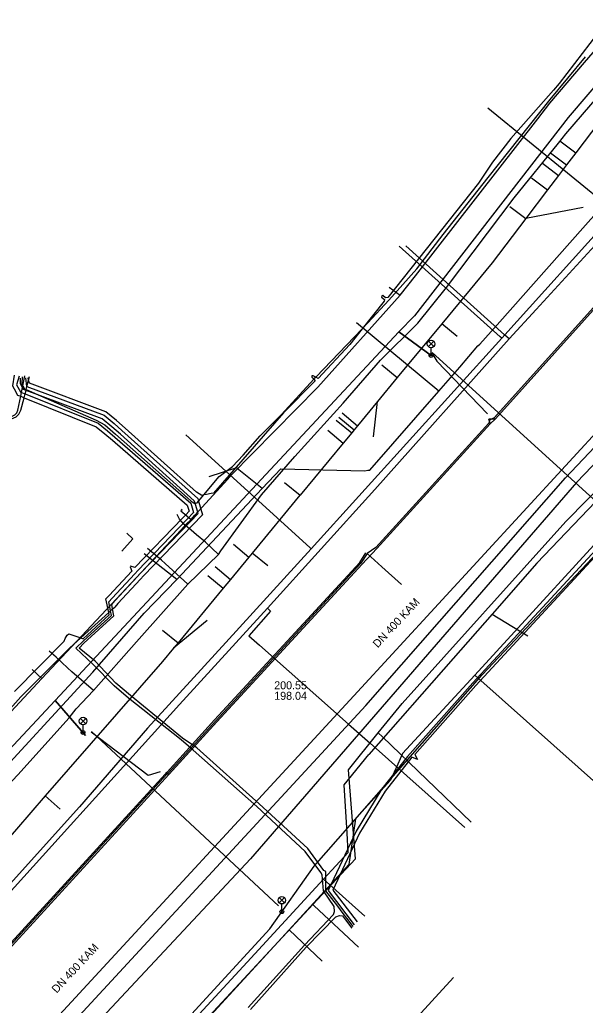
# Model space of a CAD drawing. Extents: x -598932 to -598196, y -1162210 to -1161504.
# Drawn here: x -598529.5 to -598473, y -1161698.8 to -1161600.2 of the extents above; entities that cross this region are included whole.
import ezdxf

# ---------------------------------------------------------------- set-up
doc = ezdxf.new("R2010")
doc.units = 0
for name, color, linetype in [('Vrstva 1', 7, 'Continuous'), ('Vrstva 12', 7, 'Continuous'), ('Vrstva 14', 7, 'Continuous'), ('Vrstva 16', 7, 'Continuous'), ('Vrstva 33', 7, 'Continuous'), ('Vrstva 4', 7, 'Continuous'), ('Vrstva 42', 7, 'Continuous'), ('Vrstva 54', 7, 'Continuous'), ('Vrstva 55', 7, 'Continuous'), ('Vrstva 58', 7, 'Continuous'), ('Vrstva 9', 7, 'Continuous')]:
    doc.layers.add(name, color=color, linetype=linetype)

msp = doc.modelspace()

# ---------------------------------------------------------------- linework, layer by layer
at = {"layer": 'Vrstva 1'}
for p, q in [((-598473.182, -1161619.024), (-598478.906, -1161620.112)), ((-598461.94, -1161630.69), (-598496.1, -1161667.83)), ((-598494.115, -1161641.949), (-598493.723, -1161638.404)), ((-598510.741, -1161660.297), (-598514.118, -1161663.089)), ((-598496.1, -1161667.83), (-598529.33, -1161703.86))]:
    msp.add_line(p, q, dxfattribs=at)
at = {"layer": 'Vrstva 12'}
for p, q in [((-598492.56, -1161626.98), (-598491.47, -1161627.78)), ((-598513.4, -1161651.29), (-598512.9, -1161650.7)), ((-598512.9, -1161650.7), (-598512.34, -1161650.2)), ((-598527.26, -1161666.11), (-598513.4, -1161651.29)), ((-598527.26, -1161666.11), (-598528.25, -1161665.21)), ((-598545.4, -1161685.5), (-598527.26, -1161666.11)), ((-598514.95, -1161704.72), (-598502.57, -1161691.23)), ((-598502.57, -1161691.23), (-598499.25, -1161694.38))]:
    msp.add_line(p, q, dxfattribs=at)
for points in [[(-598477.7, -1161610.13), (-598476.5, -1161608.59), (-598473.05, -1161604.51), (-598471.5, -1161602.74)], [(-598491.47, -1161627.78), (-598489.92, -1161625.84), (-598477.7, -1161610.13)], [(-598433.77, -1161610.9), (-598466.88, -1161647.08), (-598467.08, -1161647.64), (-598467.77, -1161648.05), (-598484.01, -1161665.77)], [(-598512.34, -1161650.2), (-598511.98, -1161649.77), (-598508.73, -1161646.22), (-598508.34, -1161645.78), (-598499.69, -1161636.97), (-598491.47, -1161627.78)], [(-598513.33, -1161649.16), (-598513.25, -1161649.23), (-598513.38, -1161649.33), (-598512.34, -1161650.2)], [(-598484.01, -1161665.77), (-598491.22, -1161673.61), (-598491.7, -1161674.67)], [(-598460.18, -1161686.12), (-598460.61, -1161686.59), (-598484.01, -1161665.77)], [(-598491.7, -1161674.67), (-598492.43, -1161676.27), (-598495.94, -1161680.13), (-598496.6, -1161684.71), (-598502.57, -1161691.23)]]:
    msp.add_lwpolyline(points, dxfattribs=at)
at = {"layer": 'Vrstva 14'}
for points in [[(-598597.949, -1161786.696), (-598594.355, -1161782.22), (-598591.124, -1161778.235), (-598590.488, -1161777.45), (-598568.259, -1161750.324), (-598540.145, -1161717.756), (-598494.895, -1161668.814), (-598474.946, -1161646.048), (-598446.726, -1161616.22), (-598420.512, -1161586.879), (-598391.532, -1161555.529), (-598341.416, -1161505.182)], [(-598573.404, -1161732.925), (-598571.604, -1161731.052), (-598554.514, -1161713.376), (-598533.774, -1161691.098), (-598513.523, -1161668.723), (-598504.735, -1161659.069), (-598494, -1161647.223), (-598480.574, -1161632.154), (-598477.858, -1161629.221), (-598469.826, -1161620.401), (-598456.055, -1161605.679), (-598446.117, -1161594.93), (-598428.638, -1161575.491)], [(-598449.055, -1161597.092), (-598451.08, -1161599.354), (-598469.948, -1161619.476), (-598481.318, -1161632.069), (-598500.359, -1161653.156), (-598508.903, -1161662.52), (-598516.704, -1161671.085), (-598523.517, -1161678.934), (-598531.97, -1161688.321), (-598542.658, -1161699.746), (-598544.581, -1161701.802), (-598554.215, -1161711.962), (-598572.329, -1161730.54), (-598573.411, -1161730.417), (-598574.926, -1161728.994), (-598576.936, -1161727.101), (-598579.192, -1161727.23), (-598579.92, -1161727.954)], [(-598469.948, -1161619.476), (-598470.196, -1161619.273), (-598482.701, -1161609.06)], [(-598589.947, -1161792.741), (-598577.445, -1161777.792), (-598565.596, -1161764.237), (-598559.546, -1161757.337), (-598558.635, -1161756.275), (-598558.918, -1161751.624), (-598555.314, -1161747.837), (-598550.53, -1161742.727), (-598537.985, -1161729.402), (-598525.355, -1161715.849), (-598512.719, -1161702.199), (-598500.184, -1161688.704), (-598495.944, -1161684.141), (-598496.644, -1161675.242), (-598493.647, -1161671.551), (-598491.273, -1161668.615), (-598474.912, -1161650.419), (-598466.442, -1161641.794), (-598445.99, -1161619.606), (-598438.518, -1161611.629), (-598437.483, -1161610.512)], [(-598481.318, -1161632.069), (-598481.459, -1161631.942), (-598491.568, -1161622.876)], [(-598480.574, -1161632.154), (-598480.765, -1161631.978), (-598481.026, -1161631.744), (-598490.91, -1161622.846)], [(-598500.359, -1161653.156), (-598500.505, -1161653.021), (-598512.88, -1161641.744)], [(-598519.28, -1161653.375), (-598518.192, -1161652.151), (-598518.781, -1161651.584)], [(-598504.735, -1161659.069), (-598504.434, -1161659.382), (-598506.575, -1161661.833), (-598505.52, -1161662.78), (-598496.619, -1161670.672), (-598494.477, -1161672.558), (-598485.002, -1161680.994)], [(-598493.647, -1161671.551), (-598493.244, -1161671.942), (-598484.382, -1161680.458)], [(-598500.184, -1161688.704), (-598500.048, -1161688.831), (-598495.639, -1161692.958)]]:
    msp.add_lwpolyline(points, dxfattribs=at)
at = {"layer": 'Vrstva 16'}
for p, q in [((-598487.61, -1161637.39), (-598495.83, -1161630.54)), ((-598513.79, -1161656.2), (-598517.06, -1161653.63)), ((-598499.12, -1161686.18), (-598495, -1161689.86))]:
    msp.add_line(p, q, dxfattribs=at)
for points in [[(-598560.62, -1161703.06), (-598550.73, -1161696.13), (-598543.115, -1161688.089), (-598540.89, -1161685.74), (-598535.99, -1161680.56), (-598535.6, -1161680.12), (-598533.09, -1161677.35), (-598522.17, -1161665.46), (-598517.05, -1161659.56), (-598513.79, -1161656.2), (-598505.27, -1161647.11), (-598503.39, -1161645.14), (-598494.98, -1161645.33), (-598494.68, -1161645.29), (-598494.51, -1161645.26), (-598487.61, -1161637.39), (-598485.51, -1161634.99), (-598483.69, -1161632.85), (-598483.5, -1161632.67), (-598481.515, -1161630.438), (-598473.2, -1161621.09), (-598461.78, -1161608.24)], [(-598466.05, -1161642.27), (-598477.82, -1161654.59), (-598482.27, -1161659.67), (-598486.18, -1161664.12), (-598494.61, -1161673.72)], [(-598505.27, -1161647.11), (-598507.59, -1161645.23), (-598507.83, -1161645.04), (-598510.57, -1161645.95)], [(-598482.27, -1161659.67), (-598479.54, -1161661.33), (-598478.72, -1161661.84)], [(-598511.95, -1161700.1), (-598506.77, -1161694.48), (-598499.12, -1161686.18), (-598496.65, -1161683.49), (-598496.77, -1161681.57), (-598497.07, -1161676.75), (-598494.61, -1161673.72)]]:
    msp.add_lwpolyline(points, dxfattribs=at)
at = {"layer": 'Vrstva 33'}
for p, q in [((-598488.646, -1161632.391), (-598488.116, -1161632.921)), ((-598488.646, -1161632.921), (-598488.116, -1161632.391)), ((-598488.381, -1161633.806), (-598488.381, -1161633.031)), ((-598523.425, -1161670.095), (-598522.895, -1161670.625)), ((-598523.425, -1161670.625), (-598522.895, -1161670.095)), ((-598523.16, -1161671.51), (-598523.16, -1161670.735)), ((-598503.555, -1161688.015), (-598503.025, -1161688.545)), ((-598503.555, -1161688.545), (-598503.025, -1161688.015)), ((-598503.29, -1161689.43), (-598503.29, -1161688.655))]:
    msp.add_line(p, q, dxfattribs=at)
for centre, radius in [((-598488.381, -1161632.656), 0.375), ((-598488.381, -1161633.806), 0.19), ((-598488.381, -1161633.806), 0.05), ((-598523.16, -1161670.36), 0.375), ((-598523.16, -1161671.51), 0.19), ((-598523.16, -1161671.51), 0.05), ((-598503.29, -1161688.28), 0.375), ((-598503.29, -1161689.43), 0.19), ((-598503.29, -1161689.43), 0.05)]:
    msp.add_circle(centre, radius, dxfattribs=at)
at = {"layer": 'Vrstva 42'}
for p, q in [((-598476.142, -1161607.28), (-598478.125, -1161609.529)), ((-598514.801, -1161675.525), (-598514.655, -1161675.559))]:
    msp.add_line(p, q, dxfattribs=at)
for points in [[(-598514.881, -1161675.495), (-598514.586, -1161675.706), (-598514.544, -1161675.66), (-598509.789, -1161670.451), (-598509.79, -1161670.452), (-598495.271, -1161654.682), (-598493.794, -1161653.11), (-598482.467, -1161640.638), (-598481.951, -1161640.136), (-598458.21, -1161613.742), (-598445.27, -1161599.978), (-598445.069, -1161599.756), (-598441.565, -1161595.287), (-598431.149, -1161583.871), (-598378.675, -1161526.796), (-598362.821, -1161511.358), (-598362.827, -1161511.253), (-598362.686, -1161511.241), (-598356.249, -1161505.182)], [(-598514.881, -1161675.495), (-598514.586, -1161675.706), (-598514.544, -1161675.66), (-598509.789, -1161670.451), (-598509.79, -1161670.452), (-598495.271, -1161654.682), (-598493.794, -1161653.11), (-598482.467, -1161640.638), (-598481.951, -1161640.136), (-598458.21, -1161613.742), (-598445.27, -1161599.978), (-598445.069, -1161599.756), (-598441.565, -1161595.287), (-598431.149, -1161583.871), (-598378.675, -1161526.796), (-598362.821, -1161511.358), (-598362.827, -1161511.253), (-598362.686, -1161511.241), (-598356.249, -1161505.182)], [(-598482.615, -1161640.14), (-598481.951, -1161640.136), (-598458.21, -1161613.742), (-598445.27, -1161599.978), (-598445.069, -1161599.756), (-598441.565, -1161595.287), (-598431.149, -1161583.871), (-598378.675, -1161526.796), (-598362.821, -1161511.358), (-598362.827, -1161511.253), (-598362.686, -1161511.241), (-598356.249, -1161505.182)], [(-598406.04, -1161581.87), (-598407.62, -1161583.94), (-598408.397, -1161584.168), (-598416.793, -1161593.283), (-598421.344, -1161598.244), (-598423.305, -1161600.382), (-598424.039, -1161601.179), (-598432.178, -1161610.025), (-598444.71, -1161623.962), (-598460.94, -1161641.979), (-598483.892, -1161666.804), (-598490.009, -1161673.693), (-598489.744, -1161674.222), (-598490.288, -1161673.987), (-598492.973, -1161677.375), (-598495.513, -1161681.565), (-598498.183, -1161687.257), (-598495.776, -1161690.441)], [(-598468.077, -1161596.787), (-598467.695, -1161597.11), (-598470.55, -1161600.45), (-598471.53, -1161601.39), (-598471.634, -1161601.344), (-598471.955, -1161601.07), (-598472.073, -1161601.107), (-598472.084, -1161601.226), (-598471.768, -1161601.505), (-598471.73, -1161601.61), (-598475.56, -1161606.62), (-598476.142, -1161607.28)], [(-598445.433, -1161599.698), (-598445.423, -1161599.921), (-598458.32, -1161613.64), (-598482.063, -1161640.036), (-598482.553, -1161640.291)], [(-598529.239, -1161635.943), (-598529.267, -1161636.625), (-598529.162, -1161636.839), (-598529.02, -1161637.13), (-598528.835, -1161637.211), (-598527.406, -1161637.838), (-598521.84, -1161640.28), (-598520.987, -1161640.743), (-598519.913, -1161641.664), (-598512.706, -1161648.028), (-598512.353, -1161648.365), (-598512.05, -1161648.59), (-598511.965, -1161648.579), (-598511.75, -1161648.55), (-598511.606, -1161648.379), (-598511.087, -1161647.757), (-598509.54, -1161645.91), (-598508.23, -1161644.91), (-598507.16, -1161643.76), (-598505.45, -1161641.83), (-598503.32, -1161639.71), (-598500.108, -1161636.186), (-598499.989, -1161636.055), (-598499.907, -1161635.97), (-598495.249, -1161631.131), (-598494.69, -1161630.55), (-598492.61, -1161628.29), (-598489.81, -1161625.13), (-598487.17, -1161621.71), (-598482.67, -1161616), (-598476.465, -1161608.22), (-598472.955, -1161603.94)], [(-598478.125, -1161609.529), (-598480.41, -1161612.12), (-598482.25, -1161614.46), (-598483.65, -1161616.59), (-598488.09, -1161622.2), (-598492.69, -1161628.02), (-598492.917, -1161628.04), (-598493.185, -1161627.804), (-598493.297, -1161627.858), (-598493.318, -1161627.976), (-598493.045, -1161628.217), (-598493.07, -1161628.38), (-598495.249, -1161631.131), (-598496.5, -1161632.71), (-598499.666, -1161636.113), (-598499.907, -1161635.97), (-598500.145, -1161635.828), (-598500.282, -1161635.857), (-598500.3, -1161635.986), (-598500.108, -1161636.186), (-598499.962, -1161636.338), (-598503.12, -1161639.53), (-598510.135, -1161647.574)], [(-598577.666, -1161631.059), (-598572.07, -1161632.22), (-598564.36, -1161633.75), (-598554.54, -1161635.71), (-598549.13, -1161636.87), (-598542.19, -1161638.36), (-598534.07, -1161639.91), (-598531.557, -1161640.177), (-598530.727, -1161640.228), (-598530.3, -1161640.13), (-598529.85, -1161639.93), (-598529.58, -1161639.69), (-598529.37, -1161639.29), (-598529.045, -1161638.026), (-598528.945, -1161637.64), (-598528.857, -1161637.298), (-598528.835, -1161637.211), (-598528.759, -1161636.918), (-598528.597, -1161636.287), (-598528.5, -1161635.911)], [(-598577.62, -1161630.86), (-598572.04, -1161632.01), (-598564.31, -1161633.48), (-598554.44, -1161635.51), (-598549.11, -1161636.6), (-598542.14, -1161638.07), (-598534, -1161639.67), (-598531.54, -1161639.97), (-598530.73, -1161640.02), (-598530.32, -1161639.91), (-598529.961, -1161639.753), (-598529.79, -1161639.53), (-598529.66, -1161639.26), (-598529.378, -1161637.891), (-598529.298, -1161637.499), (-598529.2, -1161637.022), (-598529.162, -1161636.839), (-598528.96, -1161635.857)], [(-598488.31, -1161633.53), (-598487.81, -1161634.38), (-598482.744, -1161639.642)], [(-598488.31, -1161633.53), (-598487.81, -1161634.38), (-598482.744, -1161639.642)], [(-598488.31, -1161633.53), (-598487.81, -1161634.38), (-598482.744, -1161639.642)], [(-598530.028, -1161635.782), (-598530.202, -1161636.857), (-598530.041, -1161637.15), (-598529.707, -1161637.759), (-598529.378, -1161637.891), (-598529.045, -1161638.026), (-598521.847, -1161640.925), (-598520.974, -1161641.649), (-598520.228, -1161642.272), (-598512.739, -1161648.784), (-598512.561, -1161649.389), (-598512.881, -1161649.735), (-598513.203, -1161650.073), (-598517.986, -1161655.021), (-598518.409, -1161654.878), (-598518.458, -1161654.936), (-598518.289, -1161655.367), (-598520.556, -1161657.807), (-598520.876, -1161658.153)], [(-598529.527, -1161635.871), (-598529.803, -1161636.752), (-598529.421, -1161637.449), (-598529.298, -1161637.499), (-598528.945, -1161637.64), (-598521.633, -1161640.582), (-598520.718, -1161641.341), (-598519.971, -1161641.964), (-598512.388, -1161648.558), (-598512.112, -1161649.496), (-598512.746, -1161650.166), (-598517.698, -1161655.298), (-598517.995, -1161655.639), (-598520.262, -1161658.079), (-598520.582, -1161658.425)], [(-598520.289, -1161658.697), (-598519.969, -1161658.351), (-598517.702, -1161655.911), (-598517.41, -1161655.576), (-598512.461, -1161650.447), (-598511.663, -1161649.604), (-598511.965, -1161648.579), (-598512.037, -1161648.334), (-598519.407, -1161641.679), (-598520.266, -1161640.927), (-598521.248, -1161640.129), (-598527.406, -1161637.838), (-598528.857, -1161637.298), (-598529.097, -1161637.209), (-598529.2, -1161637.022), (-598529.406, -1161636.646), (-598529.421, -1161636.065)], [(-598528.898, -1161636.043), (-598528.81, -1161636.899), (-598528.759, -1161636.918), (-598521.033, -1161639.776), (-598520.036, -1161640.62), (-598519.269, -1161641.296), (-598511.686, -1161648.108), (-598511.606, -1161648.379), (-598511.21, -1161649.727), (-598517.122, -1161655.854), (-598517.409, -1161656.183), (-598519.676, -1161658.623), (-598519.996, -1161658.969)], [(-598510.135, -1161647.574), (-598510.368, -1161647.612), (-598510.829, -1161647.708), (-598511.087, -1161647.757), (-598511.287, -1161647.796), (-598511.815, -1161647.467), (-598518.947, -1161641.065), (-598519.806, -1161640.313), (-598520.865, -1161639.438), (-598528.524, -1161636.59), (-598528.597, -1161636.287), (-598528.653, -1161636.055)], [(-598482.625, -1161640.144), (-598482.467, -1161640.638), (-598493.794, -1161653.11), (-598495.271, -1161654.682), (-598509.79, -1161670.452), (-598509.789, -1161670.451), (-598514.544, -1161675.66), (-598514.586, -1161675.706), (-598563.469, -1161729.131), (-598604.648, -1161774.799), (-598616.464, -1161788.466), (-598628.603, -1161803.794)], [(-598482.553, -1161640.291), (-598482.606, -1161640.568), (-598493.905, -1161653.009), (-598494.76, -1161653.62)], [(-598461.236, -1161641.709), (-598484.188, -1161666.536), (-598490.739, -1161673.912), (-598493.303, -1161677.147), (-598495.867, -1161681.375), (-598498.647, -1161687.305), (-598496.052, -1161690.741)], [(-598628.837, -1161803.606), (-598616.696, -1161788.274), (-598604.872, -1161774.601), (-598563.691, -1161728.929), (-598514.958, -1161675.668), (-598514.766, -1161675.458), (-598510.011, -1161670.249), (-598510.01, -1161670.248), (-598495.509, -1161654.498), (-598494.886, -1161653.538)], [(-598628.837, -1161803.606), (-598616.696, -1161788.274), (-598604.872, -1161774.601), (-598563.691, -1161728.929), (-598514.958, -1161675.668), (-598514.766, -1161675.458), (-598510.011, -1161670.249), (-598510.01, -1161670.248), (-598495.509, -1161654.498), (-598494.886, -1161653.538)], [(-598494.76, -1161653.62), (-598495.39, -1161654.59), (-598509.9, -1161670.35), (-598514.655, -1161675.559)], [(-598494.76, -1161653.62), (-598493.29, -1161654.948), (-598491.325, -1161656.708)], [(-598494.76, -1161653.62), (-598493.29, -1161654.948), (-598491.325, -1161656.708)], [(-598529.991, -1161667.407), (-598525.038, -1161662.385), (-598524.94, -1161662.1), (-598524.749, -1161661.788), (-598524.577, -1161661.642), (-598523.375, -1161662.053), (-598523.157, -1161662.128), (-598520.54, -1161659.756), (-598520.591, -1161659.512), (-598520.876, -1161658.153)], [(-598506.67, -1161699.01), (-598501.04, -1161692.77), (-598498.14, -1161689.71), (-598498.03, -1161689.41), (-598498.07, -1161688.89), (-598499.112, -1161687.354), (-598499.25, -1161685.75), (-598499.39, -1161685.52), (-598500.97, -1161683.4), (-598505.78, -1161678.89), (-598512.14, -1161673.26), (-598513.34, -1161672.24), (-598518.63, -1161668.07), (-598520.04, -1161666.83), (-598522.17, -1161664.67), (-598523.881, -1161663.071), (-598523.11, -1161662.356), (-598520.325, -1161659.812), (-598520.411, -1161659.348), (-598520.582, -1161658.425)], [(-598496.175, -1161690.911), (-598496.805, -1161690.076), (-598497.152, -1161689.6), (-598497.709, -1161688.883), (-598498.879, -1161687.329), (-598498.89, -1161685.41), (-598499.09, -1161685.3), (-598500.69, -1161683.12), (-598505.56, -1161678.63), (-598511.79, -1161673.03), (-598513.21, -1161672.07), (-598518.42, -1161667.81), (-598519.87, -1161666.59), (-598521.96, -1161664.37), (-598523.542, -1161663.071), (-598523.063, -1161662.584), (-598520.067, -1161659.856), (-598520.201, -1161659.156), (-598520.289, -1161658.697)], [(-598532.625, -1161671.575), (-598529.387, -1161667.947), (-598524.506, -1161663.086), (-598523.375, -1161662.053), (-598520.591, -1161659.512), (-598520.411, -1161659.348), (-598520.201, -1161659.156), (-598519.996, -1161658.969)], [(-598515.453, -1161675.424), (-598516.659, -1161675.8), (-598522.33, -1161671.47)], [(-598515.453, -1161675.424), (-598516.659, -1161675.8), (-598522.33, -1161671.47)], [(-598515.453, -1161675.424), (-598516.659, -1161675.8), (-598522.33, -1161671.47)], [(-598722.434, -1161887.506), (-598721.303, -1161887.465), (-598711.981, -1161877.933), (-598701.016, -1161865.728), (-598698.292, -1161862.397), (-598697.293, -1161861.83), (-598689.452, -1161859.77), (-598688.12, -1161859.789), (-598687.331, -1161860.531), (-598681.484, -1161865.606), (-598680.195, -1161866.255), (-598678.811, -1161865.236), (-598675.692, -1161860.773), (-598673.236, -1161858.028), (-598665.054, -1161848.125), (-598640.034, -1161817.645), (-598628.603, -1161803.794), (-598616.464, -1161788.466), (-598604.648, -1161774.799), (-598563.469, -1161729.131), (-598514.586, -1161675.706), (-598514.881, -1161675.495)], [(-598514.841, -1161675.57), (-598514.772, -1161675.687), (-598563.58, -1161729.03), (-598604.76, -1161774.7), (-598616.58, -1161788.37), (-598628.72, -1161803.7), (-598640.15, -1161817.55), (-598650.17, -1161829.78), (-598665.17, -1161848.03), (-598673.35, -1161857.93), (-598675.81, -1161860.68), (-598678.92, -1161865.13), (-598680.21, -1161866.08), (-598681.4, -1161865.48), (-598687.23, -1161860.42), (-598688.06, -1161859.64), (-598689.47, -1161859.62), (-598697.35, -1161861.69), (-598698.39, -1161862.28), (-598701.13, -1161865.63), (-598712.09, -1161877.83), (-598721.41, -1161887.36)], [(-598506.42, -1161699.19), (-598500.87, -1161692.96), (-598497.88, -1161689.93), (-598497.54, -1161689.81), (-598497.23, -1161689.83), (-598496.921, -1161690.256), (-598496.311, -1161691.061)]]:
    msp.add_lwpolyline(points, dxfattribs=at)
at = {"layer": 'Vrstva 54'}
for p, q in [((-598488.264, -1161633.495), (-598468.52, -1161651.473)), ((-598522.299, -1161671.421), (-598503.621, -1161688.841))]:
    msp.add_line(p, q, dxfattribs=at)
at = {"layer": 'Vrstva 55'}
for points in [[(-598593.724, -1161815.599), (-598601.79, -1161825.2), (-598612.66, -1161816.58), (-598605.21, -1161808.89), (-598597.75, -1161800.73), (-598596.12, -1161801.43), (-598593.55, -1161803.29), (-598583.76, -1161792.8), (-598587.73, -1161788.84), (-598556.49, -1161751.54), (-598543.66, -1161733.82), (-598504.5, -1161691.15), (-598500.07, -1161684.86), (-598483.28, -1161665.74), (-598469.525, -1161651.138), (-598469.135, -1161651.28), (-598469.525, -1161651.138), (-598431.76, -1161609.32), (-598365.821, -1161539.037), (-598342.93, -1161515.615), (-598331.661, -1161505.182)], [(-598457.4, -1161589.74), (-598474.66, -1161610.02), (-598490.04, -1161629.84), (-598491.607, -1161631.432), (-598488.381, -1161633.806), (-598491.607, -1161631.432), (-598525.95, -1161668.31), (-598522.91, -1161671.8), (-598525.95, -1161668.31), (-598548.56, -1161692.55), (-598559.49, -1161681.15), (-598556.019, -1161677.263), (-598556.805, -1161676.476)]]:
    msp.add_lwpolyline(points, dxfattribs=at)
at = {"layer": 'Vrstva 58'}
msp.add_line((-598512.7, -1161656.69), (-598509.62, -1161653.7), dxfattribs=at)
for points in [[(-598475.64, -1161612.58), (-598474.91, -1161611.65), (-598460.94, -1161595.42), (-598460.68, -1161595.06)], [(-598493.43, -1161634.29), (-598489.7, -1161630.59), (-598486.84, -1161627.01), (-598480.07, -1161618.05), (-598475.64, -1161612.58)], [(-598509.62, -1161653.7), (-598509.4, -1161653.34), (-598505.32, -1161647.75), (-598501.99, -1161643.9), (-598497.16, -1161638.59), (-598493.43, -1161634.29)], [(-598509.62, -1161653.7), (-598510.92, -1161652.48), (-598511.82, -1161651.75), (-598512.36, -1161651.28), (-598513.1, -1161650.67), (-598513.53, -1161650.18), (-598513.76, -1161649.72)], [(-598512.7, -1161656.69), (-598514.95, -1161654.6), (-598515.3, -1161654.29), (-598516.7, -1161653.11)], [(-598522.1, -1161667.31), (-598517.83, -1161662.44), (-598512.7, -1161656.69)], [(-598522.1, -1161667.31), (-598524.27, -1161665.44), (-598524.72, -1161665.03), (-598525.84, -1161663.97), (-598526.53, -1161663.37)], [(-598542.94, -1161689.94), (-598540.24, -1161686.96), (-598529.69, -1161675.75), (-598524.53, -1161670.03), (-598523.86, -1161669.15), (-598522.1, -1161667.31)], [(-598502.89, -1161714.09), (-598501.8, -1161712.67), (-598499.27, -1161709.97), (-598493.54, -1161703.83), (-598490.48, -1161700.74), (-598486.12, -1161695.99)]]:
    msp.add_lwpolyline(points, dxfattribs=at)
at = {"layer": 'Vrstva 9'}
for p, q in [((-598475.512, -1161612.331), (-598473.919, -1161613.54)), ((-598476.431, -1161613.542), (-598474.838, -1161614.751)), ((-598477.223, -1161614.585), (-598475.63, -1161615.794)), ((-598478.329, -1161616.043), (-598476.736, -1161617.252)), ((-598445.884, -1161617.098), (-598473.83, -1161646.5)), ((-598480.5, -1161618.904), (-598478.9, -1161620.104)), ((-598480.493, -1161618.895), (-598478.9, -1161620.104)), ((-598485.773, -1161631.923), (-598487.315, -1161630.649)), ((-598493.297, -1161634.748), (-598491.755, -1161636.022)), ((-598497.608, -1161639.966), (-598496.067, -1161641.241)), ((-598497.265, -1161639.551), (-598495.723, -1161640.825)), ((-598497.851, -1161640.26), (-598496.309, -1161641.534)), ((-598498.698, -1161641.287), (-598497.156, -1161642.56)), ((-598473.83, -1161646.5), (-598506.43, -1161684.15)), ((-598503.016, -1161646.512), (-598501.474, -1161647.786)), ((-598508.118, -1161652.689), (-598506.576, -1161653.962)), ((-598504.703, -1161654.835), (-598506.245, -1161653.561)), ((-598509.965, -1161654.923), (-598508.423, -1161656.197)), ((-598510.691, -1161655.802), (-598509.149, -1161657.076)), ((-598515.201, -1161661.26), (-598513.659, -1161662.534)), ((-598525.434, -1161679.172), (-598526.935, -1161677.85)), ((-598506.43, -1161684.15), (-598539.1, -1161719.04))]:
    msp.add_line(p, q, dxfattribs=at)
for points in [[(-598453.06, -1161586.06), (-598454.33, -1161587.733), (-598458.955, -1161593.826), (-598460.031, -1161595.244), (-598463.665, -1161600.031), (-598473.919, -1161613.54), (-598474.838, -1161614.751), (-598475.63, -1161615.794), (-598476.736, -1161617.252), (-598478.9, -1161620.104), (-598478.906, -1161620.112), (-598482.26, -1161624.53)], [(-598482.26, -1161624.53), (-598487.315, -1161630.649), (-598491.755, -1161636.022), (-598493.723, -1161638.404), (-598495.723, -1161640.825), (-598496.067, -1161641.241), (-598496.309, -1161641.534), (-598497.156, -1161642.56), (-598501.474, -1161647.786), (-598501.475, -1161647.787), (-598506.245, -1161653.561), (-598506.576, -1161653.962), (-598508.423, -1161656.197), (-598509.149, -1161657.076), (-598513.659, -1161662.534), (-598514.118, -1161663.089), (-598515.2, -1161664.4)], [(-598515.2, -1161664.4), (-598526.935, -1161677.85), (-598529.823, -1161681.159), (-598534.89, -1161686.968), (-598544.811, -1161698.34), (-598545.587, -1161699.229)]]:
    msp.add_lwpolyline(points, dxfattribs=at)

# ---------------------------------------------------------------- texts
at = {"layer": 'Vrstva 4'}
for p in [(-598493.703, -1161663.09), (-598525.794, -1161697.63)]:
    msp.add_text('DN 400 KAM', height=0.8, rotation=47, dxfattribs=at).set_placement(p)
for s, p in [('200.55', (-598504.052, -1161667.186)), ('198.04', (-598504.052, -1161668.236))]:
    msp.add_text(s, height=0.8, dxfattribs=at).set_placement(p)

doc.saveas('drawing.dxf')
